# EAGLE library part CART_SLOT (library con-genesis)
Cartridge Connector
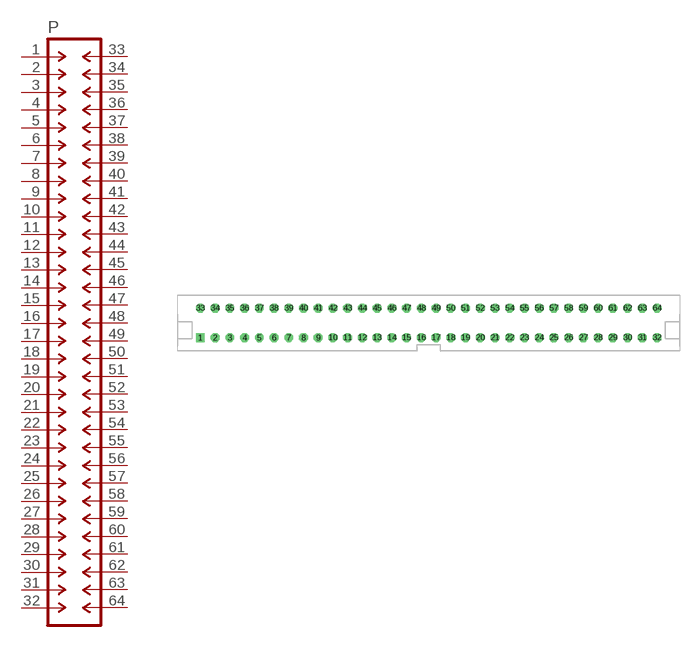
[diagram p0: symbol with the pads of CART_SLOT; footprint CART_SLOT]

Designator prefix P

## CART_SLOT  [CART_SLOT]
1  1  pas
2  2  pas
3  3  pas
4  4  pas
5  5  pas
6  6  pas
7  7  pas
8  8  pas
9  9  pas
10  10  pas
11  11  pas
12  12  pas
13  13  pas
14  14  pas
15  15  pas
16  16  pas
17  17  pas
18  18  pas
19  19  pas
20  20  pas
21  21  pas
22  22  pas
23  23  pas
24  24  pas
25  25  pas
26  26  pas
27  27  pas
28  28  pas
29  29  pas
30  30  pas
31  31  pas
32  32  pas
33  33  pas
34  34  pas
35  35  pas
36  36  pas
37  37  pas
38  38  pas
39  39  pas
40  40  pas
41  41  pas
42  42  pas
43  43  pas
44  44  pas
45  45  pas
46  46  pas
47  47  pas
48  48  pas
49  49  pas
50  50  pas
51  51  pas
52  52  pas
53  53  pas
54  54  pas
55  55  pas
56  56  pas
57  57  pas
58  58  pas
59  59  pas
60  60  pas
61  61  pas
62  62  pas
63  63  pas
64  64  pas

## Footprint CART_SLOT (pad centres in mm)
HEADER - 0.1" vertical, latching
drill 1.016 square: 1 -39.37,-1.27
drill 1.016 octagon: 2 -36.83,-1.27; 3 -34.29,-1.27; 4 -31.75,-1.27; 5 -29.21,-1.27; 6 -26.67,-1.27; 7 -24.13,-1.27; 8 -21.59,-1.27; 9 -19.05,-1.27; 10 -16.51,-1.27; 11 -13.97,-1.27; 12 -11.43,-1.27; 13 -8.89,-1.27; 14 -6.35,-1.27; 15 -3.81,-1.27; 16 -1.27,-1.27; 17 1.27,-1.27; 18 3.81,-1.27; 19 6.35,-1.27; 20 8.89,-1.27; 21 11.43,-1.27; 22 13.97,-1.27; 23 16.51,-1.27; 24 19.05,-1.27; 25 21.59,-1.27; 26 24.13,-1.27; 27 26.67,-1.27; 28 29.21,-1.27; 29 31.75,-1.27; 30 34.29,-1.27; 31 36.83,-1.27; 32 39.37,-1.27; 33 -39.37,3.81; 34 -36.83,3.81; 35 -34.29,3.81; 36 -31.75,3.81; 37 -29.21,3.81; 38 -26.67,3.81; 39 -24.13,3.81; 40 -21.59,3.81; 41 -19.05,3.81; 42 -16.51,3.81; 43 -13.97,3.81; 44 -11.43,3.81; 45 -8.89,3.81; 46 -6.35,3.81; 47 -3.81,3.81; 48 -1.27,3.81; 49 1.27,3.81; 50 3.81,3.81; 51 6.35,3.81; 52 8.89,3.81; 53 11.43,3.81; 54 13.97,3.81; 55 16.51,3.81; 56 19.05,3.81; 57 21.59,3.81; 58 24.13,3.81; 59 26.67,3.81; 60 29.21,3.81; 61 31.75,3.81; 62 34.29,3.81; 63 36.83,3.81; 64 39.37,3.81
